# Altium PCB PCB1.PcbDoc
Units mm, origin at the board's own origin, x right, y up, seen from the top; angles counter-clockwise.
Board outline 152.4 x 101.6 mm, 4 copper layers (Top Layer, Internal Plane 1, Internal Plane 2, Bottom Layer); 32 components, 39 nets, 152 pads, 0 vias.
Unrouted connection lines stored in the file: 3.
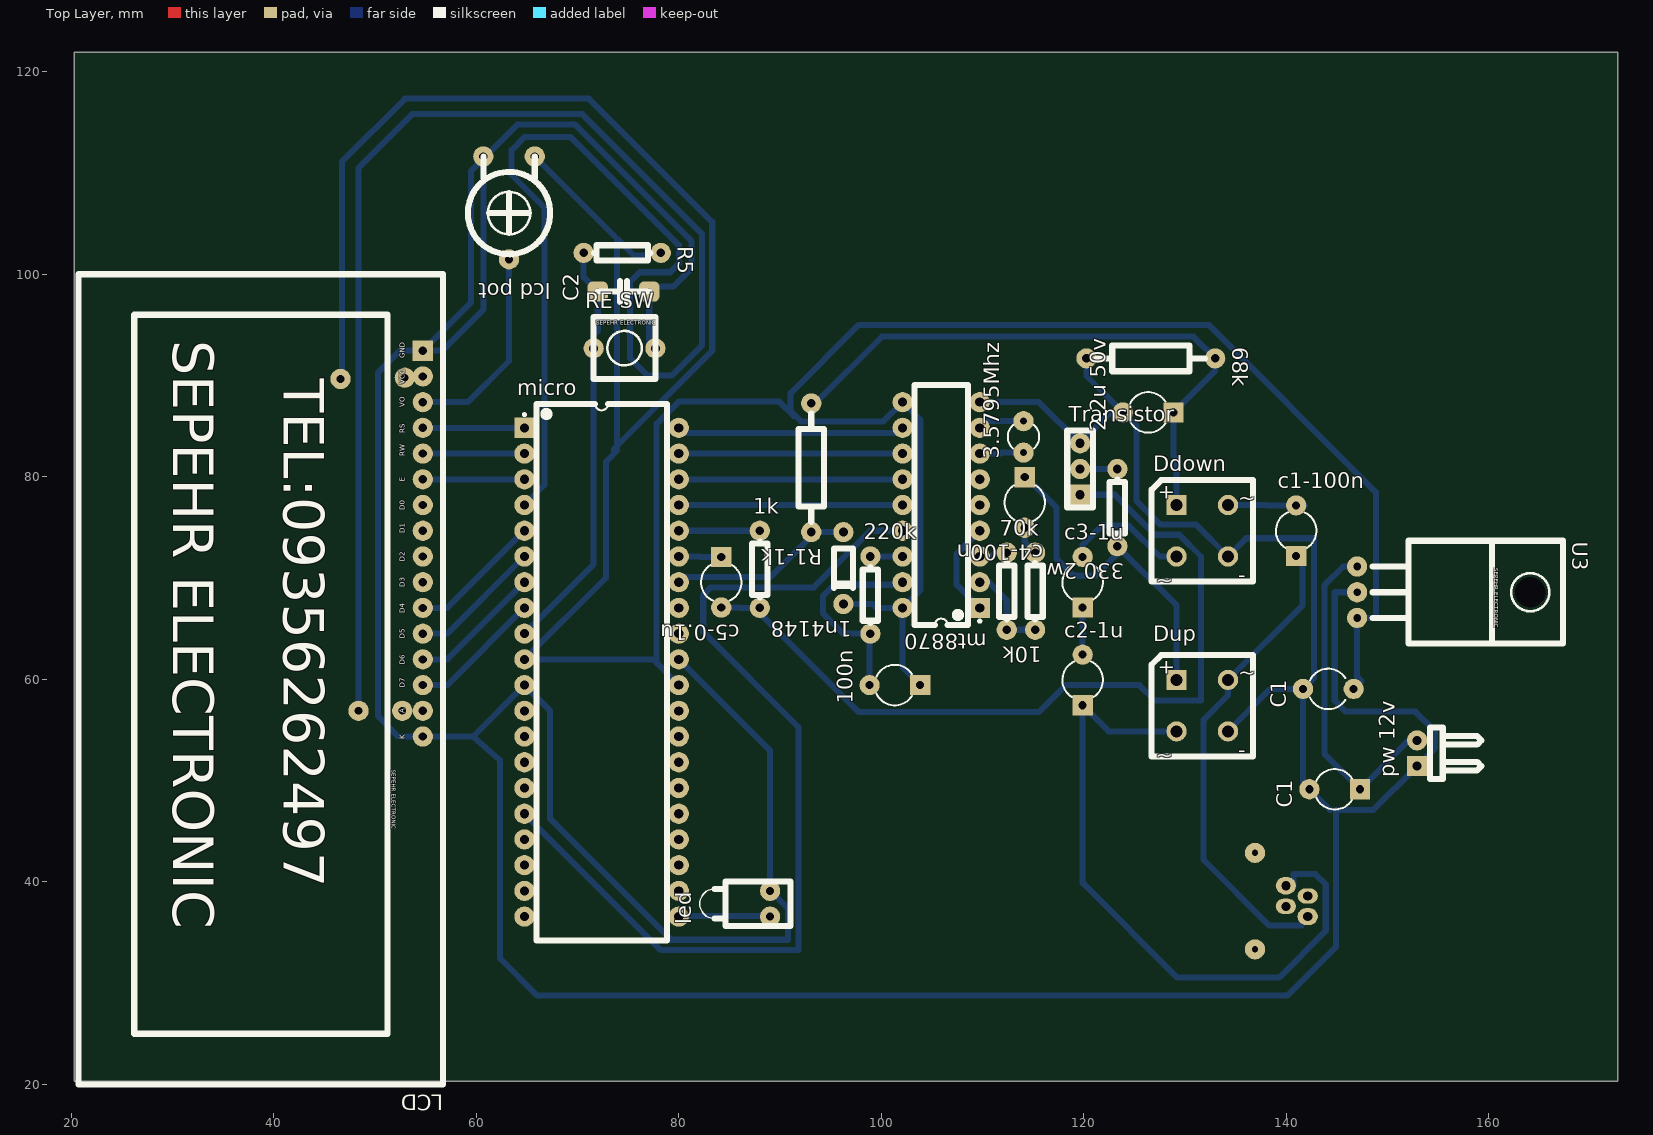
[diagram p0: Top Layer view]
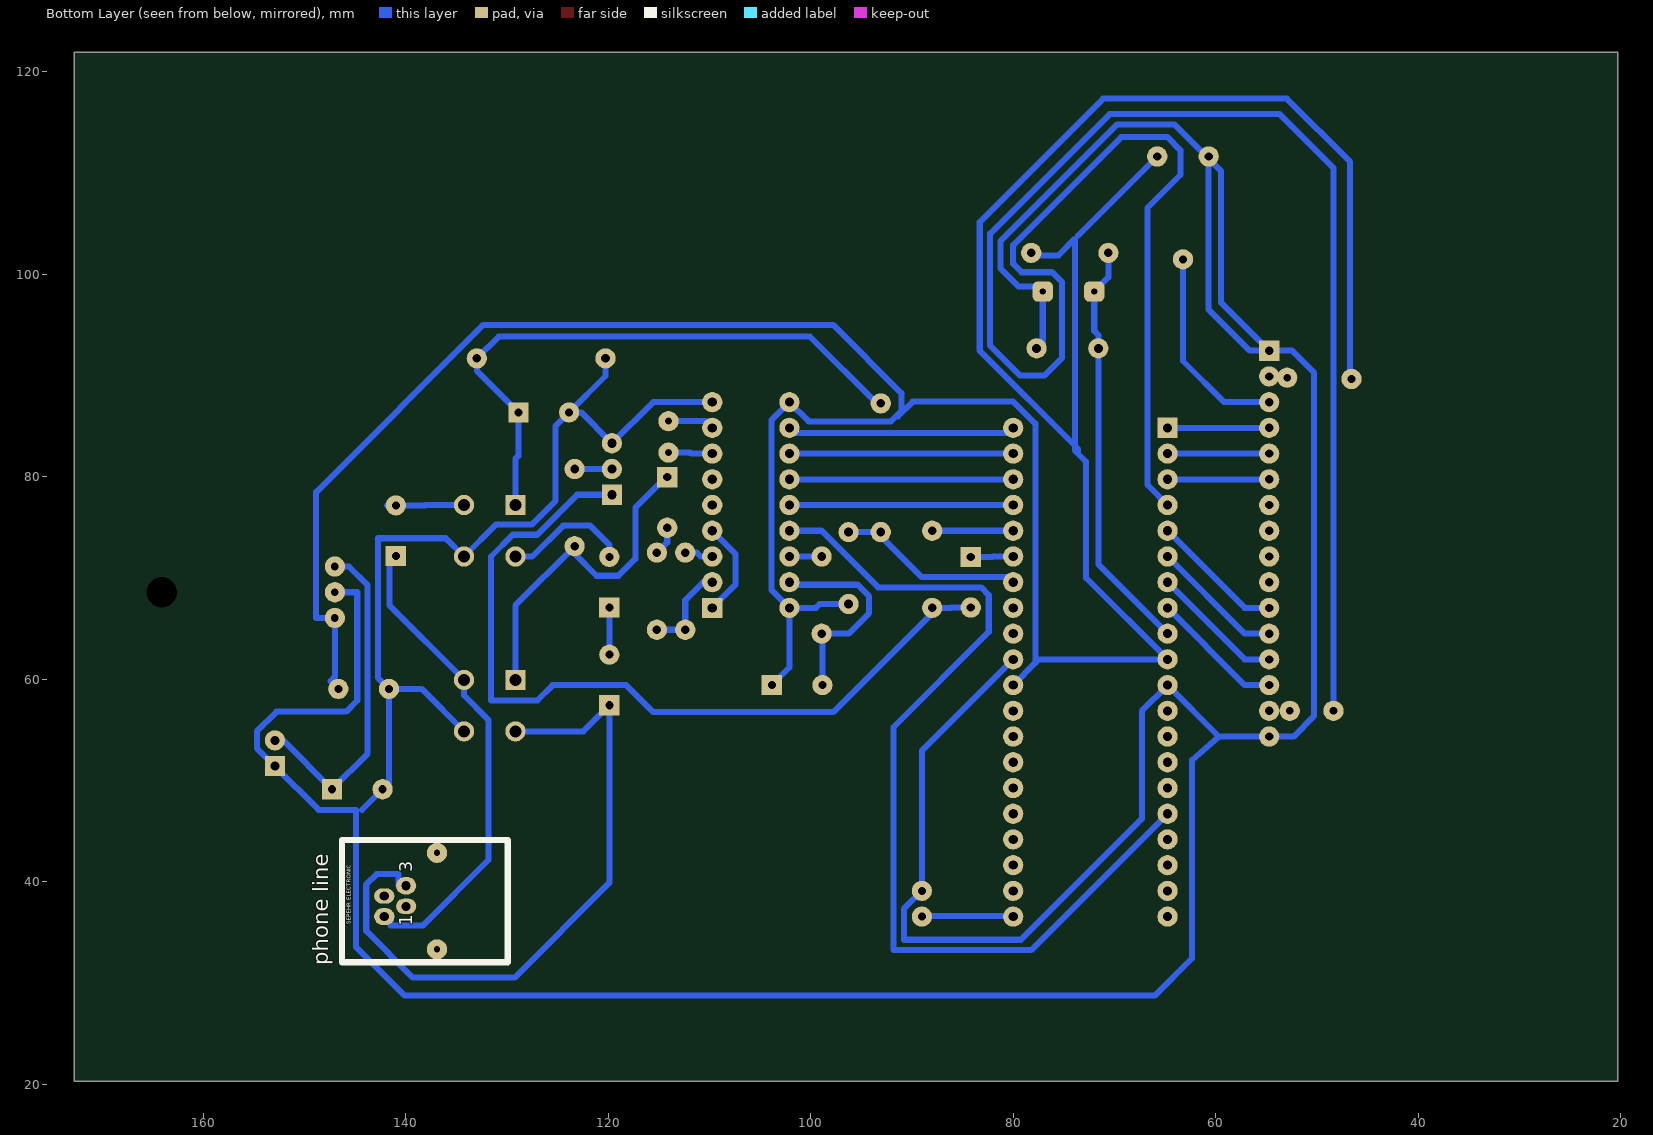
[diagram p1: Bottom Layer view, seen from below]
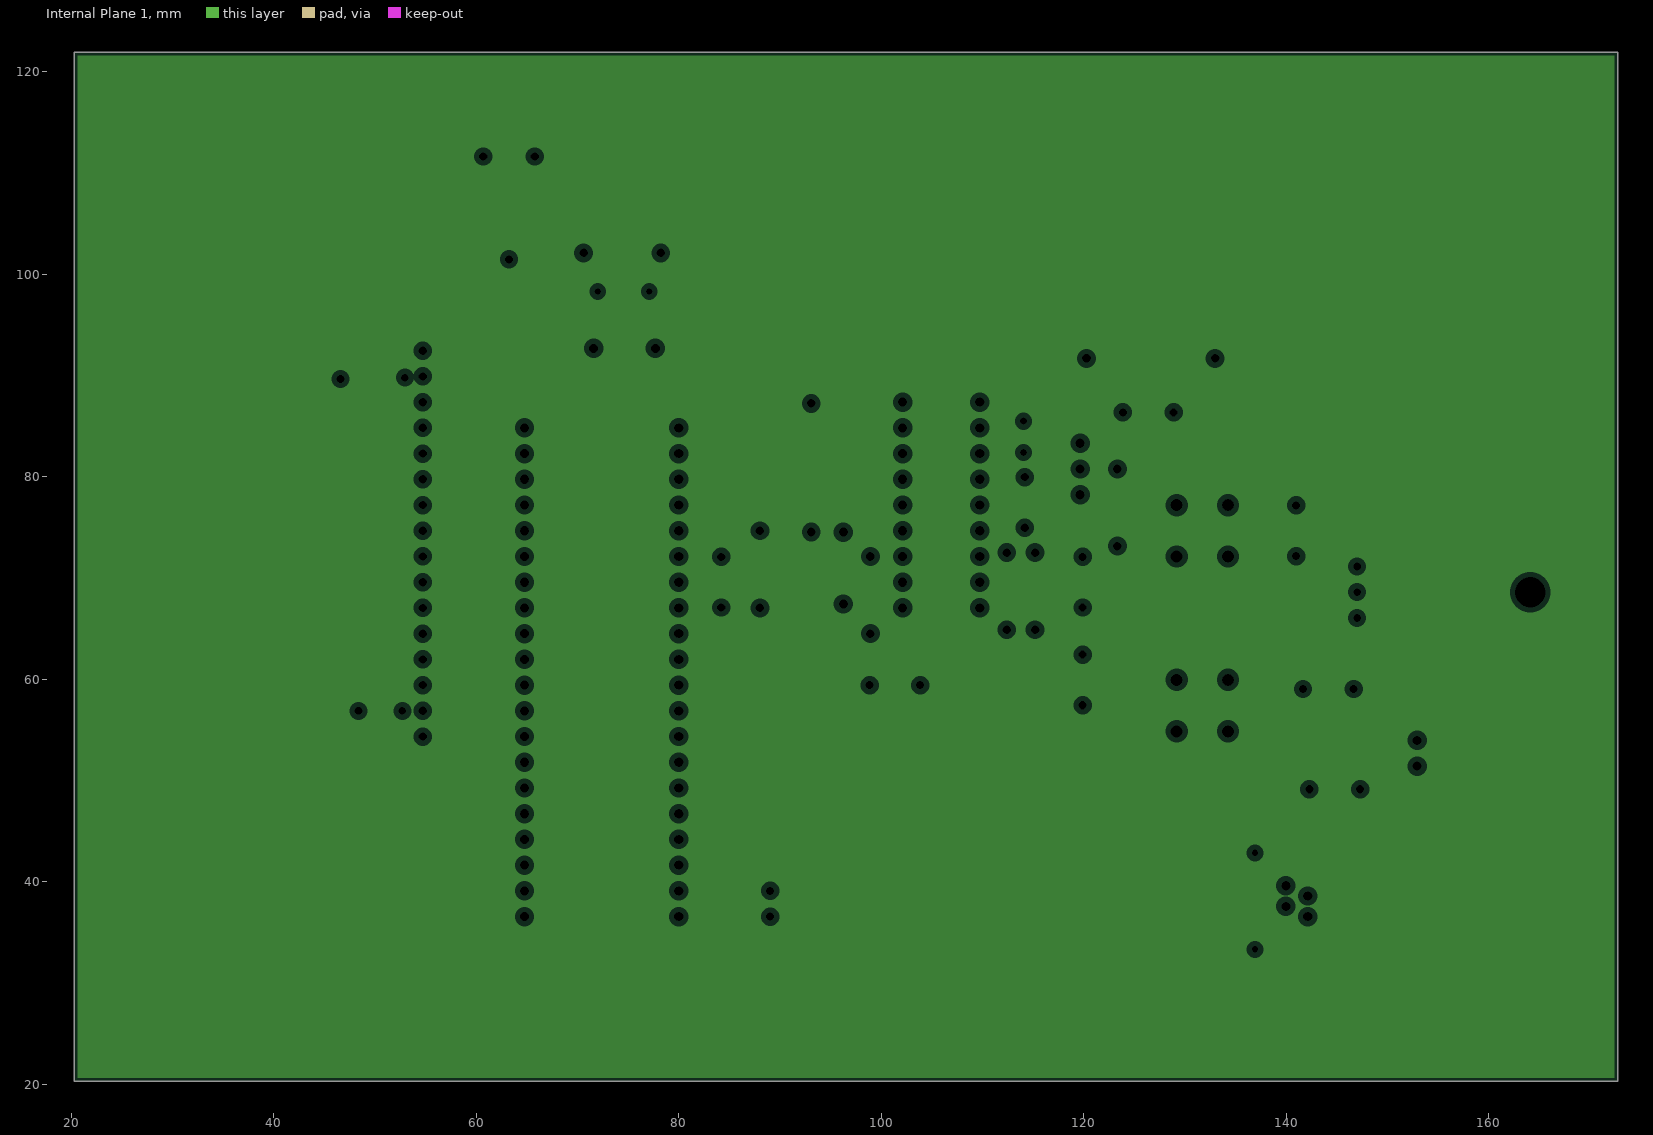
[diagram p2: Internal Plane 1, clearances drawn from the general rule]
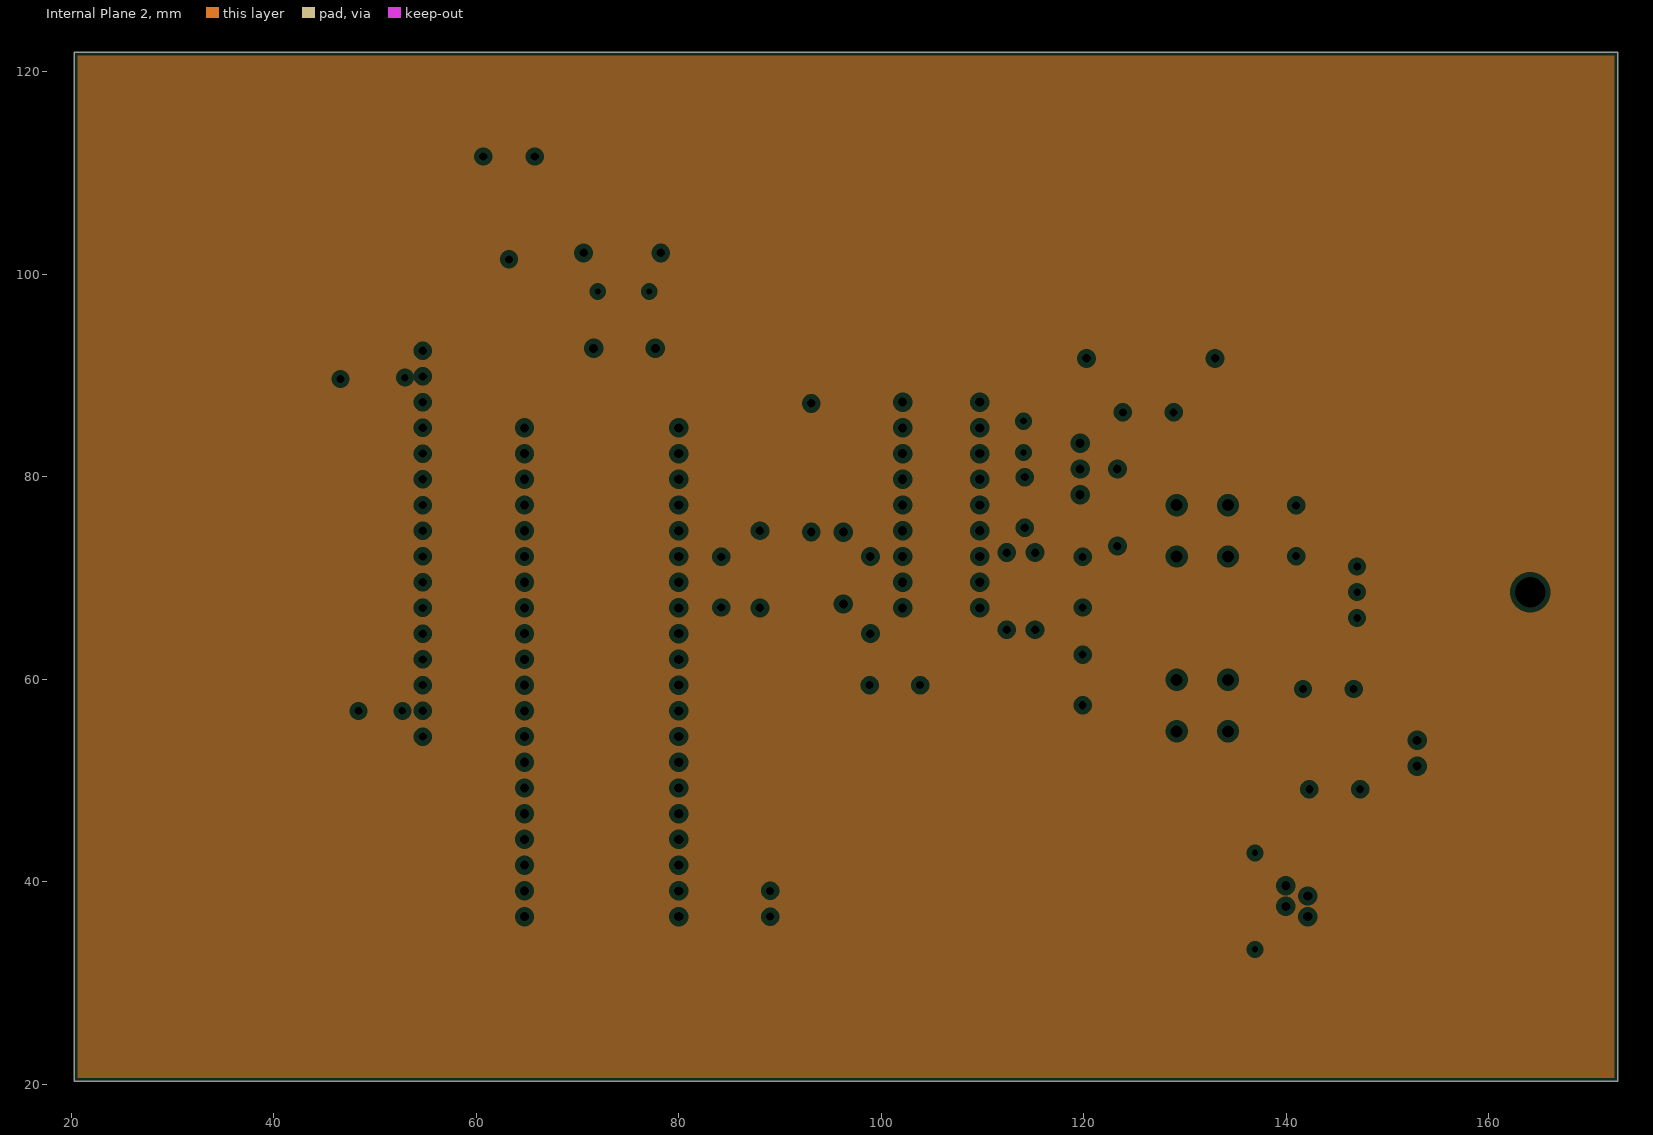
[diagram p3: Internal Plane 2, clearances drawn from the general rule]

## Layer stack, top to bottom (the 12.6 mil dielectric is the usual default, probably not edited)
Top Layer: signal copper 0.0356
Dielectric: dielectric 0.32, FR-4, Dk 4.8
Internal Plane 1: plane copper 0.0356
Dielectric: dielectric 0.32, FR-4, Dk 4.8
Internal Plane 2: plane copper 0.0356
Dielectric: dielectric 0.32, FR-4, Dk 4.8
Bottom Layer: signal copper 0.0356

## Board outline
20.32,20.32 172.72,20.32 172.72,121.92 20.32,121.92

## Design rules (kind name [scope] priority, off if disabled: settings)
AssemblyTestPointUsage AssemblyTestPointUsage_1 [All] p2:
AssemblyTestpoint AssemblyTestpoint_1 [All] p2: testpointundercomponent=TRUE minsize=1.016 maxsize=2.54 preferedsize=1.524 minholesize=0 maxholesize=1.016 preferedholesize=0.813 testpointgrid=0.025 usegrid=TRUE gridtolerance=0 allowsidetop=TRUE allowsidebottom=TRUE
Clearance [All] p1: gap=0.4
ComponentClearance ComponentClearance_1 [All] p2: gap=0.254 collisioncheckmode=3 verticalgap=0.254 showdistances=FALSE
DiffPairsRouting DiffPairsRouting_1 [All] p2: maxlimit=0.254 minlimit=0.254 mostfreqgap=0.254 maxuncoupledlength=12.7
FabricationTestPointUsage TestPointUsage [All] p2: valid=0 allowmultiple=FALSE
FabricationTestpoint Testpoint [All] p2: side=3 testpointundercomponent=TRUE minsize=1.016 maxsize=2.54 preferedsize=1.524 minholesize=0 maxholesize=1.016 preferedholesize=0.813 testpointgrid=0.025 allowsidetop=TRUE allowsidebottom=TRUE usegrid=TRUE gridtolerance=0
FanoutControl Fanout_LCC [IsLCC] p1: bgadir=Out bgaviamode=Centered fanoutstyle=Auto fanoutdirection=Alternating viagrid=0.025 // Fanout_LCC (Default Rule)
FanoutControl Fanout_BGA [IsBGA] p2: bgadir=Out bgaviamode=Centered fanoutstyle=Auto fanoutdirection=Alternating viagrid=0.025 // Fanout_BGA (Default Rule)
FanoutControl Fanout_Small [(CompPinCount < 5)] p3: bgadir=Out bgaviamode=Centered fanoutstyle=Auto fanoutdirection=OutThenIn viagrid=0.025 // Fanout_Small (Default Rule)
FanoutControl Fanout_SOIC [IsSOIC] p4: bgadir=Out bgaviamode=Centered fanoutstyle=Auto fanoutdirection=Alternating viagrid=0.025 // Fanout_SOIC (Default Rule)
FanoutControl Fanout_BGA_1 [IsBGA] p6: bgadir=Out bgaviamode=Centered fanoutstyle=Auto fanoutdirection=Alternating viagrid=0.025 // Fanout_BGA (Default Rule)
FanoutControl Fanout_LCC_1 [IsLCC] p7: bgadir=Out bgaviamode=Centered fanoutstyle=Auto fanoutdirection=Alternating viagrid=0.025 // Fanout_LCC (Default Rule)
FanoutControl Fanout_SOIC_1 [IsSOIC] p8: bgadir=Out bgaviamode=Centered fanoutstyle=Auto fanoutdirection=Alternating viagrid=0.025 // Fanout_SOIC (Default Rule)
FanoutControl Fanout_Small_1 [(CompPinCount < 5)] p9: bgadir=Out bgaviamode=Centered fanoutstyle=Auto fanoutdirection=OutThenIn viagrid=0.025 // Fanout_Small (Default Rule)
FanoutControl Fanout_Default_1 [All] p10: bgadir=Out bgaviamode=Centered fanoutstyle=Auto fanoutdirection=Alternating viagrid=0.025 // Fanout_Default (Default Rule)
Height Height_1 [All] p2: minheight=0 maxheight=25.4 prefheight=12.7
HoleSize HoleSize_1 [All] p2: absolutevalues=TRUE maxlimit=2.54 minlimit=0.025 maxpercent=80.000 minpercent=20.000
HoleToHoleClearance HoleToHoleClearance_1 [All] p2: gap=0.254 allowstackedmicrovias=TRUE
LayerPairs LayerPairs_1 [All] p2: enforce=TRUE
MinimumSolderMaskSliver MinimumSolderMaskSliver_1 [All] p2: minsoldermaskwidth=0.254
NetAntennae NetAntennae_1 [All] p2: netantennaetolerance=0
PasteMaskExpansion PasteMaskExpansion_1 [All] p2: expansion=0
PlaneClearance [All] p1: clearance=0.508
PlaneClearance PlaneClearance_1 [All] p2: clearance=0.508
PlaneConnect [All] p1: planeconnectstyle=Relief reliefexpansion=0.508 reliefentries=4 reliefconductorwidth=0.254 reliefairgap=0.254
PolygonConnect [All] p1: connectstyle=Relief reliefconductorwidth=0.254 reliefentries=4 polygonreliefangle="90 Angle"
PolygonConnect PolygonConnect_1 [All] p2: connectstyle=Relief reliefconductorwidth=0.254 reliefentries=4 polygonreliefangle="90 Angle"
RoutingLayers [All] p1: top layer_v5=FALSE bottom layer_v5=TRUE
RoutingPriority RoutingPriority_1 [All] p2: routingpriority=0
RoutingTopology RoutingTopology_1 [All] p2: topology=Shortest
RoutingVias [All] p1: holewidth=0.8 width=2 viastyle="Through Hole" minholewidth=0.711 minwidth=1.27 maxholewidth=0.711 maxwidth=1.27
ShortCircuit ShortCircuit_1 [All] p2: allowed=FALSE
SilkToSilkClearance SilkToSilkClearance_1 [All] p2: silktosilkclearance=0.254
SilkscreenOverComponentPads [All] p1: minsilkscreentomaskgap=0.254
SilkscreenOverComponentPads SilkscreenOverComponentPads_1 [All] p2: minsilkscreentomaskgap=0.254
SolderMaskExpansion [All] p1: expansion=0.102
SolderMaskExpansion SolderMaskExpansion_1 [All] p2: expansion=0.102
UnRoutedNet UnRoutedNet_1 [All] p2:
Width [All] p1: maxlimit=0.4 minlimit=0.4 preferedwidth=0.4
20 further rules are at their usual default settings.

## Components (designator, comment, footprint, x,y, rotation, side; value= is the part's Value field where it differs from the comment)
1k "Res1" AXIAL-0.3 88.011,70.866 r90 top
1n4148 "Diode 1N914" DO-35 96.266,70.993 r270 top
"2.2u 50v" "Cap2" CAPR5-4X5#1 126.365,86.36 r180 top
3.5795Mhz "XTAL" R38 114.046,83.947 r180 top
10k "Res1" AXIAL-0.3 115.189,68.707 r270 top
68k "Res Semi" AXIAL-0.5 126.619,91.694 r0 top
70k "Res1" AXIAL-0.3 112.395,68.707 r90 top
100n "Cap2" CAPR5-4X5#1 101.346,59.436 r180 top
220k "Res1" AXIAL-0.3 98.933,68.326 r90 top
"330 2w" "Res1" AXIAL-0.3 123.317,76.962 r270 top
C1 "Cap1" CAPR5-4X5#1 144.78,49.149 r180 top
C1 "Cap1" CAPR5-4X5#2 144.145,59.055 r180 top
c1-100n "Cap2" CAPR5-4X5#1 140.97,74.676 r90 top
C2 "" CAP1 77.089,98.298 r180 top
c2-1u "Cap2" CAPR5-4X5#1 119.888,59.944 r90 top
c3-1u "Cap2" CAPR5-4X5#1 119.888,69.596 r90 top
c4-100n "Cap2" CAPR5-4X5#1 114.173,77.47 r270 top
c5-0.1u "Cap2" CAPR5-4X5#1 84.201,69.596 r270 top
Ddown "Bridge1" D-38 131.699,74.676 r0 top
Dup "Bridge1" D-38 131.699,57.404 r0 top
LCD "Header 16" lcd2*16 46.355,70.358 r270 top
"lcd pot" "POT" pot1 63.246,101.473 r180 top
led "LED1" LED-1 89.027,37.846 r180 top
micro "ATmega16-16PC" 40P6 72.39,60.706 r0 top
mt8870 "SW DIP-9" DIP-18 105.918,77.216 r180 top
"phone line" "Header 4H" "JACK LINE" 142.113,38.1 r90 bottom
"pw 12v" "Header 2H" HDR1X2H 152.908,51.435 r90 top
R1-1k "Res Semi" AXIAL-0.5 93.091,80.899 r270 top
R5 "Res1" AXIAL-0.3 74.422,102.108 r0 top
"RE SW" "sw1" MICROSWITCH4 71.628,92.71 r0 top
Transistor "Header 3" HDR1X3 119.634,78.232 r90 top
U3 "MC7805BT" REG2 158.496,72.009 r270 top

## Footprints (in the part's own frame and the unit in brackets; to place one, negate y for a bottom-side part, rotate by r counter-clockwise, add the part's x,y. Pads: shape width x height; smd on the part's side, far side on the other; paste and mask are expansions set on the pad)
40P6 [mm] "DIP, 40-Leads, Row Spacing 15.24mm, Pitch 2.54mm, Body 52.2x13.95mm"
  rect 2x2 hole 0.9: 1(-7.62,24.13)
  round 2 hole 0.9: 2(-7.62,21.59) 3(-7.62,19.05) 4(-7.62,16.51) 5(-7.62,13.97) 6(-7.62,11.43) 7(-7.62,8.89) 8(-7.62,6.35) 9(-7.62,3.81) 10(-7.62,1.27) 11(-7.62,-1.27) 12(-7.62,-3.81) 13(-7.62,-6.35) 14(-7.62,-8.89) 15(-7.62,-11.43) 16(-7.62,-13.97) 17(-7.62,-16.51) 18(-7.62,-19.05) 19(-7.62,-21.59) 20(-7.62,-24.13) 21(7.62,-24.13) 22(7.62,-21.59) 23(7.62,-19.05) 24(7.62,-16.51) 25(7.62,-13.97) 26(7.62,-11.43) 27(7.62,-8.89) 28(7.62,-6.35) 29(7.62,-3.81) 30(7.62,-1.27) 31(7.62,1.27) 32(7.62,3.81) 33(7.62,6.35) 34(7.62,8.89) 35(7.62,11.43) 36(7.62,13.97) 37(7.62,16.51) 38(7.62,19.05) 39(7.62,21.59) 40(7.62,24.13)
  silkscreen extent -7.74,-26.5 6.45,26.5, body extent -7.05,-26.47 7.05,26.47, height 4.83
AXIAL-0.3 [mm] "Axial Device, Thru-Hole; 2 Leads; 0.3 in Pin Spacing"
  round 2 hole 0.85: 1(-3.81,0) 2(3.81,0)
  silkscreen extent -2.77,-0.76 2.77,0.76
AXIAL-0.5 [mm] "Axial Device, Thru-Hole; 2 Leads; 0.5 in Pin Spacing"
  round 2 hole 0.85: 1(-6.35,0) 2(6.35,0)
  silkscreen extent -5.33,-1.27 5.33,1.27
CAP1 [mm]
  rrect50% 2x2 hole 0.635: 1(0,0) 2(5.08,0)
  silkscreen extent 0,-1.05 5.08,1.05
CAPR5-4X5#1 [mm] "Capacitor; 2 Leads"
  rect 2x2 hole 0.8: 1(-2.5,0)
  round 2 hole 0.8: 2(2.5,0)
  silkscreen extent -1.69,-2 1.82,2
CAPR5-4X5#2 [mm] "Capacitor; 2 Leads"
  round 2 hole 0.8: 1(-2.5,0) 2(2.5,0)
  silkscreen extent -1.69,-2 1.82,2
D-38 [mm] "Bridge Rectifier; 4 Terminals; Body 9.4 x 9.4 mm (typ); Pitch 5.08 mm"
  rect 2x2 hole 1.2: 1(-2.54,2.54)
  round 2 hole 1.2: 2(-2.54,-2.54) 3(2.54,-2.54) 4(2.54,2.54)
  silkscreen extent -5,-5 5,5, body extent -5,-5 5,5, height 9.91
DIP-18 [mm] "DIP; 18 Leads; Row Spacing 7.62 mm; Pitch 2.54 mm"
  rect 2x2 hole 0.9: 1(-3.81,10.16)
  round 2 hole 0.9: 2(-3.81,7.62) 3(-3.81,5.08) 4(-3.81,2.54) 5(-3.81,0) 6(-3.81,-2.54) 7(-3.81,-5.08) 8(-3.81,-7.62) 9(-3.81,-10.16) 10(3.81,-10.16) 11(3.81,-7.62) 12(3.81,-5.08) 13(3.81,-2.54) 14(3.81,0) 15(3.81,2.54) 16(3.81,5.08) 17(3.81,7.62) 18(3.81,10.16)
  silkscreen extent -3.94,-11.85 2.65,11.85, body extent -3.6,-11.8 3.6,11.8, height 5.08
DO-35 [mm] "Diode, Axial; Body 3.8 x 1.9 mm (LxDia. max), Lead Dia. 0.53 mm (max)"
  round 2 hole 0.9: 1(-3.55,0) 2(3.55,0)
  silkscreen extent -1.95,-0.95 2.05,0.95
HDR1X2H [mm] "Connector; Header; 2 Position; Right Angle"
  rect 2x2 hole 0.9: 1(0,0)
  round 2 hole 0.9: 2(2.54,0)
  silkscreen extent -1.27,-6.35 3.81,-1.27
HDR1X3 [mm] "Connector; Header; 3 Position"
  rect 2x2 hole 0.9: 1(0,0)
  round 2 hole 0.9: 2(2.54,0) 3(5.08,0)
  silkscreen extent -1.27,-1.27 6.35,1.27
"JACK LINE" [mm]
  oval 1.5x2 hole 0.9: 1(-0.508,-2.159) 4(0.508,0)
  oval 1.7x2 hole 0.9: 2(-1.524,0) 3(1.524,-2.159)
  round 2 hole 0.635: 7(-4.763,-5.207) 8(4.763,-5.207)
  silkscreen extent -6.03,-12.19 6.03,4.19
lcd2*16 [mil]
  round 78.74 on Top Overlay: 1(-1072.76,314.25) 1(-1072.76,-914.09) 1(1887.87,314.25) 1(1887.87,-914.09)
  rect 78.74x78.74 hole 32: 1(-870,330)
  round 78.74 hole 32: 2(-770,330) 3(-670,330) 4(-570,330) 5(-470,330) 6(-370,330) 7(-270,330) 8(-170,330) 9(-70,330) 10(30,330) 11(130,330) 12(230,330) 13(330,330) 14(430,330) 15(530,330) 16(630,330)
  silkscreen extent -1167,-1009 1982,409
LED-1 [mm] "LED; 2 Leads"
  round 2 hole 0.8: 1(0,1.27) 2(0,-1.27)
  silkscreen extent -2,-2.2 6.95,2.2
MICROSWITCH4 [mm]
  round 2 hole 0.9: 1(-0.025,-0.025) 2(6.075,-0.025)
  silkscreen extent -0.03,-3.05 6.07,3.05
pot1 [mm]
  round 2 hole 0.8: 1(-2.54,-10.16) 2(2.54,-10.16) 3(0,0)
  silkscreen extent -4.06,-10.16 4.06,-0.51
R38 [mm] "Crystal, Thru-Hole; 2 Leads; Body 3.1 x 8.2 mm (Dia.xH)"
  round 2 hole 0.7: 1(0,1.55) 2(0,-1.55)
  silkscreen extent -1.55,-1.19 1.55,1.17
REG2 [mm]
  round 2 hole 3: 0(3.404,5.588)
  round 2 hole 0.76: 1(0.863,-11.507) 2(3.403,-11.507) 3(5.943,-11.507)
  silkscreen extent -1.68,-9.98 8.48,8.81

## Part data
1k 10k 70k 220k "330 2w" R5: "Resistor"
1n4148: "High Conductance Fast Diode"
"2.2u 50v" 100n c1-100n c2-1u c3-1u c4-100n c5-0.1u: "Capacitor"
3.5795Mhz: "Crystal Oscillator"
68k R1-1k: "Semiconductor Resistor"
C1 C1 C2: library part Cap2, "Capacitor"
Ddown Dup: "Full Wave Diode Bridge"
LCD: "Header, 16-Pin"
"lcd pot": library part "Header 3", "Header, 3-Pin"
led: "Typical RED GaAs LED"
micro: "8-Bit AVR Microcontroller with 16K Bytes of In-System Programmable Flash Memory"
mt8870: "DIP Switch, 9 Position, SPST"
"phone line": "Header, 4-Pin, Right Angle"
"pw 12v": "Header, 2-Pin, Right Angle"
"RE SW": library part "Header 2", "Header, 2-Pin"
Transistor: "Header, 3-Pin"
U3: "3-Terminal Positive Fixed Voltage Regulator"

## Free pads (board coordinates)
  round 2 hole 0.762: 0(46.609,89.662) 1(52.959,89.789) 2(48.387,56.896) 3(52.705,56.896)

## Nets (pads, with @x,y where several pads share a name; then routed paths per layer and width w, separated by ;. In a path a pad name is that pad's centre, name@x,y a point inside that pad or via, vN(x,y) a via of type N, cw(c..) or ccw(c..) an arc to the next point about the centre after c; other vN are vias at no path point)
GND: 68k.1 "2.2u 50v.2" "lcd pot.2" "pw 12v.1" "RE SW.2" C1.2 C2.1 Ddown.3 Dup.3 LCD.1@54.737,92.456 LCD.16 led.2 micro.11 micro.31 mt8870.9 Transistor.3 U3.2 | length 468.5
  Bottom Layer w0.6: 60.706,111.633 60.706,111.404 ; 77.703,92.685 77.089,92.685 C2.1 77.597,98.806 79.502,98.806 81.28,100.584 81.28,103.251 69.723,114.808 64.11,114.808 60.706,111.404 ; micro.31 89.027,52.959 led.2 90.805,37.338 90.805,34.29 79.248,34.29 67.31,46.228 67.31,56.896 micro.11 59.69,54.356 ; mt8870.9 115.57,87.376 Transistor.3 122.682,86.36 123.865,86.36 ; 68k.1 120.269,89.956 123.865,86.36 ; Dup.3 138.43,59.055 C1.2@141.645,59.055 ; 144.312,47.117 141.645,49.784 C1.2@141.645,59.055 ; U3.2 144.78,68.606 144.78,57.912 145.872,56.82 152.73,56.82 154.686,54.864 154.686,53.213 152.908,51.435 148.579,47.106 144.907,47.106 144.907,33.604 140.081,28.778 66.04,28.778 62.357,32.461 62.357,52.019 59.69,54.356 ; LCD.1@54.737,92.456 52.476,92.456 50.292,90.272 50.292,56.388 52.324,54.356 LCD.16 59.69,54.356 ; LCD.1@54.737,92.456 59.487,97.206 59.487,110.185 60.706,111.404 ; LCD.1@54.737,92.456 56.642,92.456 60.706,96.52 60.706,111.404 ; 123.865,86.36 125.222,85.003 125.222,77.597 127.508,75.311 131.064,75.311 Ddown.3 136.042,73.939 142.748,73.939 142.748,60.158 C1.2@141.645,59.055
LED: LCD.15 micro.4 pad.2 pad.3 | length 188.3
  Bottom Layer w0.6: pad.2 48.387,110.515 53.696,115.824 70.485,115.824 82.296,104.013 82.296,92.964 79.35,90.018 76.911,90.018 75.184,91.745 75.184,99.212 76.175,100.203 79.176,100.203 80.01,101.037 80.01,102.87 69.342,113.538 64.77,113.538 63.5,112.268 63.5,109.804 66.751,106.553 66.751,79.197 micro.4
Net1k_1: 1k.1 c5-0.1u.2 Transistor.1 | length 82.4
  Bottom Layer w0.6: c5-0.1u.2 86.081,67.096 86.121,67.056 1k.1 88.011,66.548 97.79,56.769 115.57,56.769 118.237,59.436 125.476,59.436 127,57.912 131.572,57.912 131.572,72.136 129.427,74.281 127.014,74.281 123.063,78.232 Transistor.1
Net1k_2: 1k.2 micro.36 | length 8
  Bottom Layer w0.6: micro.36 1k.2
Net1n4148_1: 1n4148.1 micro.34 R1-1k.2 | length 18.6
  Bottom Layer w0.6: micro.34 80.518,70.104 89.027,70.104 93.472,74.549 94.971,74.549 94.977,74.543 1n4148.1@96.52,74.543
"Net2.2u 50v_1": 68k.2 "2.2u 50v.1" Ddown.1 R1-1k.1 | length 59.4
  Bottom Layer w0.6: R1-1k.1@93.472,87.249 100.076,93.853 130.81,93.853 68k.2 132.969,90.464 128.865,86.36 128.865,82.082 129.159,81.788 Ddown.1
Net3.5795Mhz_1: 3.5795Mhz.1 mt8870.7 | length 4.4
  Bottom Layer w0.6: mt8870.7 111.836,82.296 111.937,82.397 3.5795Mhz.1
Net3.5795Mhz_2: 3.5795Mhz.2 mt8870.8 | length 4.6
  Bottom Layer w0.6: mt8870.8 110.389,85.497 3.5795Mhz.2
Net10k_1: 10k.1 c4-100n.2 | length 3
  Bottom Layer w0.6: c4-100n.2@114.173,75.097 114.173,73.533 10k.1
Net10k_2: 10k.2 70k.1 mt8870.2 | length 9.1
  Bottom Layer w0.6: mt8870.2 110.617,69.596 112.395,67.818 70k.1 10k.2
Net70k_2: 70k.2 mt8870.3 | length 2.8
  Bottom Layer w0.6: mt8870.3 110.871,72.136 111.252,72.517 70k.2
Net100n_2: 100n.2 220k.1 mt8870.17 | length 20.6
  Bottom Layer w0.6: 100n.2 98.846,64.476 98.806,64.516 96.266,64.516 94.234,66.548 94.234,68.199 95.377,69.342 101.854,69.342 mt8870.17
Net220k_2: 220k.2 mt8870.16 | length 3.3
  Bottom Layer w0.6: 220k.2@98.806,72.136 mt8870.16
"Net330 2w_1": "330 2w.1" Transistor.2 | length 3.7
  Bottom Layer w0.6: Transistor.2 123.317,80.772
"Net330 2w_2": "330 2w.2" c4-100n.1 Dup.1 | length 33.5
  Bottom Layer w0.6: c4-100n.1@114.173,80.097 117.323,76.947 117.323,71.907 118.999,70.231 121.158,70.231 123.317,72.39 123.317,73.152 129.159,67.31 Dup.1
Netc1-100n_1: "phone line.2" c1-100n.1 Dup.4 | length 47.7
  Bottom Layer w0.6: c1-100n.1@141.605,71.922 141.605,67.31 Dup.4 134.239,58.42 131.826,56.007 131.826,42.164 138.303,35.687 141.478,35.687 141.478,36.576 142.113,36.576
Netc1-100n_2: c1-100n.2 Ddown.4 | length 7.6
  Bottom Layer w0.6: Ddown.4 138.024,77.216 138.064,77.176 c1-100n.2@141.859,77.176
NetC1_1: "pw 12v.2" C1.1@147.28,49.149 U3.1 | length 33.2
  Bottom Layer w0.6: U3.1 145.619,71.146 143.764,69.291 143.764,52.665 147.28,49.149 152.106,53.975 152.908,53.975
Netc2-1u_1: "phone line.3" c2-1u.1 Dup.2 | length 67.8
  Bottom Layer w0.6: Dup.2 122.468,54.864 c2-1u.1 119.888,39.903 129.235,30.556 139.281,30.556 143.891,35.166 143.891,39.751 142.875,40.767 140.716,40.767 140.716,39.624 139.954,39.624
Netc2-1u_2: c2-1u.2 c3-1u.1 | length 4.7
  Bottom Layer w0.6: c2-1u.2 c3-1u.1
Netc3-1u_2: c3-1u.2 Ddown.2 | length 12.5
  Bottom Layer w0.6: c3-1u.2 119.888,73.279 121.793,75.184 124.46,75.184 127.508,72.136 Ddown.2
Netc5-0.1u_1: c5-0.1u.1 micro.35 | length 4.2
  Bottom Layer w0.6: micro.35 82.067,72.136 82.107,72.096 c5-0.1u.1
NetLCD_3: "lcd pot.3" LCD.3 | length 20.2
  Bottom Layer w0.6: LCD.3 59.182,87.376 63.246,91.44 63.246,101.473
Netled_1: led.1 micro.21 | length 9.1
  Bottom Layer w0.6: micro.21 80.086,36.652 88.951,36.652 led.1
Netmicro_16: micro.16 mt8870.15 | length 93.9
  Bottom Layer w0.6: micro.16 78.232,33.274 91.821,33.274 91.821,55.296 82.423,64.694 82.423,68.326 83.185,69.088 93.345,69.088 98.933,74.676 mt8870.15
Netmicro_37: micro.37 mt8870.14 | length 22.1
  Bottom Layer w0.6: micro.37 mt8870.14
Netmicro_38: micro.38 mt8870.13 | length 22.1
  Bottom Layer w0.6: micro.38 mt8870.13
Netmicro_39: micro.39 mt8870.12 | length 22.1
  Bottom Layer w0.6: micro.39 mt8870.12
Netmicro_40: micro.40 mt8870.11 | length 22.5
  Bottom Layer w0.6: micro.40 80.518,84.328 101.6,84.328 mt8870.11
Netmt8870_1: mt8870.1 mt8870.4 | length 9.5
  Bottom Layer w0.6: mt8870.1 107.442,69.342 107.442,72.39 mt8870.4
PIN1: LCD.4 micro.1 | length 10
  Bottom Layer w0.6: LCD.4 micro.1
PIN2: LCD.5 micro.2 | length 10
  Bottom Layer w0.6: LCD.5 micro.2
PIN3: LCD.6 micro.3 | length 10
  Bottom Layer w0.6: LCD.6 micro.3
PIN4: LCD.11 micro.5 | length 13.2
  Bottom Layer w0.6: LCD.11 57.15,67.056 micro.5
PIN5: LCD.12 micro.6 | length 13.2
  Bottom Layer w0.6: LCD.12 57.15,64.516 micro.6
PIN6: LCD.13 micro.7 | length 13.2
  Bottom Layer w0.6: LCD.13 57.15,61.976 micro.7
PIN7: LCD.14 micro.8 | length 13.2
  Bottom Layer w0.6: LCD.14 57.15,59.436 micro.8
RESET: "RE SW.1" C2.2 micro.9 R5.1 | length 40.9
  Bottom Layer w0.6: micro.9 71.603,71.349 71.603,92.685 71.603,94.006 72.009,94.412 C2.2 70.612,99.695 R5.1@70.612,101.854
VCC: 1n4148.2 100n.1 "lcd pot.1" C1.1@146.645,59.055 LCD.2 micro.10 micro.30 mt8870.10 mt8870.18 pad.0 pad.1 R5.2 U3.3 | length 347.8
  Bottom Layer w0.6: pad.0@46.736,89.916 46.736,111.1 52.984,117.348 71.12,117.348 83.312,105.156 83.312,92.456 73.609,82.753 73.609,82.296 ; 65.786,111.633 73.609,103.81 ; R5.2@78.232,101.854 75.565,101.854 73.914,103.505 73.914,82.601 73.609,82.296 ; micro.30 77.826,61.62 ; 91.389,85.979 89.941,87.427 80.01,87.427 77.826,85.242 77.826,61.62 ; 1n4148.2@96.52,67.443 99.111,67.443 99.498,67.056 mt8870.18 ; 100n.1 102.108,61.174 mt8870.18 ; C1.1@146.645,59.055 147.421,59.831 146.989,60.262 U3.3 148.844,66.066 148.844,78.486 132.334,94.996 97.79,94.996 91.059,88.265 91.059,86.487 92.075,85.471 100.203,85.471 mt8870.10 103.886,85.598 103.886,68.834 mt8870.18 ; 73.609,82.296 72.822,81.509 72.822,70.028 micro.10 77.47,61.976 77.826,61.62
pads on no net: "phone line.1" "phone line.4" "phone line.7" "phone line.8" LCD.1@23.137,22.406 LCD.1@23.137,97.606 LCD.1@54.337,22.406 LCD.1@54.337,97.606 LCD.7 LCD.8 LCD.9 LCD.10 micro.12 micro.13 micro.14 micro.15 micro.17 micro.18 micro.19 micro.20 micro.22 micro.23 micro.24 micro.25 micro.26 micro.27 micro.28 micro.29 micro.32 micro.33 mt8870.5 mt8870.6 U3.0

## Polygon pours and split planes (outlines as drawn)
no net on Internal Plane 1 (split plane): 172.419,20.621 20.621,20.621 20.621,121.619 172.419,121.619
no net on Internal Plane 2 (split plane): 172.419,20.621 20.621,20.621 20.621,121.619 172.419,121.619

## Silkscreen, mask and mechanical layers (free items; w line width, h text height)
Mechanical 16:
  drawing of 1873 lines, arcs and shapes, not listed
  text "1" at 36.246,189.611 h1.78
  text "2" at 108.89,189.611 h1.78
  text "3" at 182.042,189.611 h1.78
  text "4" at 254.94,189.611 h1.78
  text "A" at 1.905,166.599 h1.78
  text "A" at 288.925,166.599 h1.78
  text "B" at 1.905,118.542 h1.78
  text "B" at 288.925,118.542 h1.78
  text "C" at 136.728,81.534 h1.78 r90
  text "C" at 1.905,70.028 h1.78
  text "ENGINEER:" at 7.874,45.593 h1.14
  text "TITLE:" at 45.974,45.593 h1.14
  text "PCB DESIGNER:" at 7.874,38.1 h1.14
  text "D" at 133.604,34.595 h1.78
  text "D" at 1.905,22.022 h1.78
  text "DATE:" at 173.99,17.78 h1.14
  text "PART NO.:" at 212.09,17.78 h1.14
  text "REV:" at 265.43,17.78 h1.14
  text "Altium Limited" at 140.97,15.24 h1.78
  text ".PRINT_DATE" at 175.26,14.732 h1.78
  text "12a Rodborough Rd" at 140.97,12.7 h1.78
  text "Frenchs Forest" at 140.97,10.16 h1.78
  text "FILE NAME:" at 173.99,10.16 h1.14
  text "DWG NO:" at 212.09,10.16 h1.14
  text "SCALE:" at 265.43,10.16 h1.14
  text "NSW 2086" at 140.97,7.62 h1.78
  text ".PCB_FILE_NAME_NO_PATH" at 175.26,7.112 h1.78
  text "1" at 36.246,1.651 h1.78
  text "2" at 108.89,1.651 h1.78
  text "3" at 182.042,1.651 h1.78
  text "4" at 254.94,1.651 h1.78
